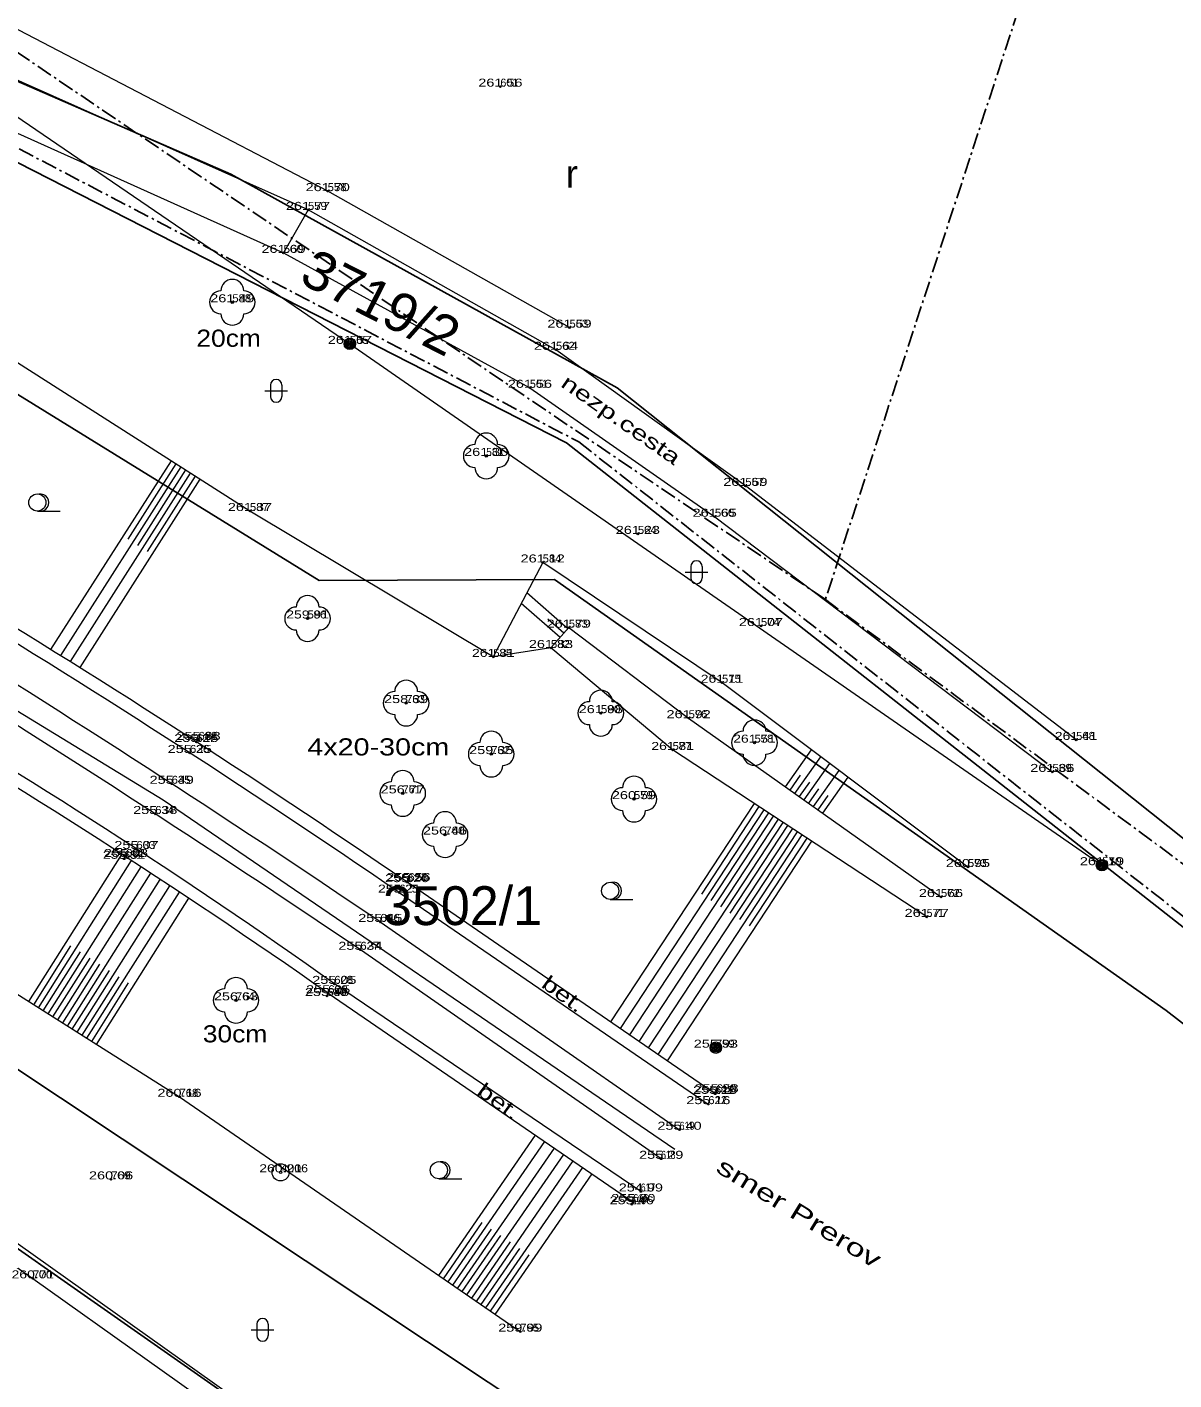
# Model space of a CAD drawing. Extents: x -568530 to -568223, y -1154101 to -1153740.
# Drawn here: x -568377.8 to -568327.6, y -1153975.4 to -1153916.3 of the extents above; entities that cross this region are included whole.
import ezdxf
from ezdxf.enums import TextEntityAlignment as Align

# ---------------------------------------------------------------- set-up
doc = ezdxf.new("R2010")
doc.units = 0
doc.header["$LTSCALE"] = 0.14
doc.header["$PDMODE"] = 32
doc.header["$PDSIZE"] = 0.07
doc.linetypes.add('DOT_DASHED', pattern=[7.7, 5, -1.2, 0.3, -1.2])
for name, color, linetype, lineweight in [('1', 7, 'Continuous', 25), ('11', 7, 'Continuous', 13), ('12', 7, 'Continuous', 13), ('14', 7, 'Continuous', 13), ('15', 7, 'Continuous', 13), ('21', 7, 'Continuous', 13), ('22', 7, 'Continuous', 13), ('23', 7, 'Continuous', 13), ('25', 7, 'Continuous', 13), ('36', 7, 'Continuous', 13), ('4', 7, 'Continuous', 25), ('42', 7, 'Continuous', 13), ('51', 7, 'Continuous', 13), ('52', 7, 'Continuous', 13), ('53', 7, 'Continuous', 13), ('6', 7, 'DOT_DASHED', 25), ('7', 7, 'Continuous', 13)]:
    doc.layers.add(name, color=color, linetype=linetype, lineweight=lineweight)
for name, color, linetype in [('13', 7, 'Continuous'), ('18', 7, 'Continuous'), ('40', 7, 'Continuous')]:
    doc.layers.add(name, color=color, linetype=linetype)

msp = doc.modelspace()

# ---------------------------------------------------------------- linework, layer by layer
at = {"layer": '1'}
for points in [[(-568393.92, -1153911.77), (-568368.85, -1153922.7), (-568351.96, -1153932.04), (-568287.81, -1153983.13)], [(-568397.85, -1153916.62), (-568382.3, -1153920.09), (-568354.17, -1153934.45), (-568269.88, -1154000.68)], [(-568381.21, -1153967.57), (-568365.54, -1153978.53), (-568303.79, -1154025.76)]]:
    msp.add_lwpolyline(points, dxfattribs=at)
at = {"layer": '11'}
for p, q in [((-568381.39, -1153919.46), (-568366.54, -1153926.14)), ((-568331.89, -1153947.44), (-568346.35, -1153936.33)), ((-568347.69, -1153937.68), (-568332.93, -1153948.84)), ((-568361.48, -1153954.12), (-568347.97, -1153963.37)), ((-568347.67, -1153962.92), (-568361.14, -1153953.66)), ((-568350.92, -1153967.19), (-568364.32, -1153958.11)), ((-568364.59, -1153958.52), (-568351.25, -1153967.65))]:
    msp.add_line(p, q, dxfattribs=at)
for points in [[(-568346.35, -1153936.33), (-568354.63, -1153930.38), (-568365.47, -1153924.26), (-568380.39, -1153917.61)], [(-568365.47, -1153924.26), (-568366.54, -1153926.14), (-568355.77, -1153932.04), (-568347.69, -1153937.68)]]:
    msp.add_lwpolyline(points, dxfattribs=at)
for centre, radius, start, end in [((-568603.2448, -1154307.4258), 428.6782, 55.61365, 58.88779), ((-568594.3404, -1154293.2988), 411.4198, 55.52877, 58.93604), ((-568515.3815, -1154170.2907), 260.4616, 54.55112, 59.87018), ((-568546.6395, -1154219.0038), 317.7953, 55.0507, 59.41916)]:
    msp.add_arc(centre, radius, start, end, dxfattribs=at)
for p in [(-568357.06, -1153918.87), (-568364.61, -1153923.44), (-568365.47, -1153924.26), (-568366.54, -1153926.14), (-568368.78, -1153928.3), (-568354.04, -1153929.41), (-568363.64, -1153930.12), (-568354.63, -1153930.38), (-568355.77, -1153932.04), (-568357.68, -1153935.02), (-568346.35, -1153936.33), (-568368.01, -1153937.43), (-568347.69, -1153937.68), (-568351.05, -1153938.43), (-568355.21, -1153939.68), (-568365.49, -1153942.13), (-568354.07, -1153942.53), (-568345.67, -1153942.46), (-568354.85, -1153943.42), (-568357.37, -1153943.81), (-568347.37, -1153944.94), (-568361.18, -1153945.83), (-568352.67, -1153946.27), (-568348.83, -1153946.49), (-568370.35, -1153947.53), (-568370.26, -1153947.44), (-568345.95, -1153947.56), (-568331.89, -1153947.44), (-568370.64, -1153948.01), (-568357.46, -1153948.06), (-568349.53, -1153947.88), (-568332.93, -1153948.84), (-568371.43, -1153949.36), (-568361.33, -1153949.78), (-568351.22, -1153950.03), (-568372.15, -1153950.68), (-568359.48, -1153951.58), (-568372.97, -1153952.21), (-568373.51, -1153952.64), (-568373.43, -1153952.56), (-568336.62, -1153953), (-568330.76, -1153952.92), (-568361.08, -1153953.61), (-568361.48, -1153954.12), (-568361.14, -1153953.66), (-568337.8, -1153954.31), (-568362.31, -1153955.4), (-568338.42, -1153955.18), (-568363.18, -1153956.62), (-568364.32, -1153958.11), (-568368.62, -1153958.83), (-568364.64, -1153958.64), (-568364.59, -1153958.52), (-568347.64, -1153960.9), (-568371.09, -1153963.05), (-568347.67, -1153962.92), (-568347.61, -1153962.85), (-568347.97, -1153963.37), (-568349.23, -1153964.49), (-568350.03, -1153965.76), (-568374.08, -1153966.66), (-568350.92, -1153967.19), (-568351.32, -1153967.75), (-568351.25, -1153967.65), (-568377.5, -1153970.99), (-568356.19, -1153973.32)]:
    msp.add_point(p, dxfattribs=at)
at = {"layer": '12'}
for p, q in [((-568362.31, -1153955.4), (-568349.23, -1153964.49)), ((-568350.03, -1153965.76), (-568363.18, -1153956.62))]:
    msp.add_line(p, q, dxfattribs=at)
for centre, radius, start, end in [((-568708.2241, -1154467.802), 618.2333, 55.97737, 58.24225), ((-568727.54, -1154497.0975), 651.8237, 56.01434, 58.14955)]:
    msp.add_arc(centre, radius, start, end, dxfattribs=at)
at = {"layer": '14'}
for points in [[(-568354.85, -1153943.42), (-568357.37, -1153943.81), (-568368.01, -1153937.43), (-568378.86, -1153930.51), (-568388.51, -1153923.88), (-568398.65, -1153916.93)], [(-568415.48, -1153937.58), (-568406.64, -1153941.73), (-568392.63, -1153949.25), (-568382.59, -1153955.78), (-568371.09, -1153963.05), (-568356.19, -1153973.32)], [(-568336.62, -1153953), (-568347.37, -1153944.94), (-568355.21, -1153939.68), (-568357.37, -1153943.81)], [(-568338.42, -1153955.18), (-568349.53, -1153947.88), (-568354.85, -1153943.42), (-568354.07, -1153942.53), (-568348.83, -1153946.49), (-568337.8, -1153954.31)]]:
    msp.add_lwpolyline(points, dxfattribs=at)
at = {"layer": '15'}
for p, q in [((-568371.459, -1153935.23), (-568376.724, -1153943.485)), ((-568371.038, -1153935.499), (-568376.299, -1153943.749)), ((-568370.616, -1153935.768), (-568375.875, -1153944.014)), ((-568371.248, -1153935.365), (-568373.354, -1153938.665)), ((-568370.827, -1153935.633), (-568372.931, -1153938.933)), ((-568370.195, -1153936.037), (-568375.452, -1153944.279)), ((-568370.405, -1153935.902), (-568372.509, -1153939.2)), ((-568354.116, -1153942.582), (-568355.907, -1153941.012)), ((-568354.445, -1153942.958), (-568356.145, -1153941.468)), ((-568354.281, -1153942.77), (-568354.979, -1153942.158)), ((-568344.601, -1153949.488), (-568343.457, -1153947.874)), ((-568344.193, -1153949.777), (-568343.056, -1153948.174)), ((-568343.785, -1153950.067), (-568342.656, -1153948.474)), ((-568343.377, -1153950.356), (-568342.256, -1153948.774)), ((-568344.397, -1153949.633), (-568343.941, -1153948.989)), ((-568343.989, -1153949.922), (-568343.536, -1153949.283)), ((-568342.969, -1153950.645), (-568341.856, -1153949.074)), ((-568343.581, -1153950.211), (-568343.131, -1153949.576)), ((-568343.173, -1153950.5), (-568342.726, -1153949.87)), ((-568345.966, -1153950.222), (-568352.243, -1153959.776)), ((-568345.548, -1153950.496), (-568351.831, -1153960.059)), ((-568345.757, -1153950.359), (-568348.269, -1153954.183)), ((-568345.339, -1153950.634), (-568347.854, -1153954.461)), ((-568345.13, -1153950.771), (-568351.419, -1153960.343)), ((-568344.712, -1153951.046), (-568351.007, -1153960.626)), ((-568344.921, -1153950.908), (-568347.438, -1153954.739)), ((-568344.503, -1153951.183), (-568347.022, -1153955.017)), ((-568344.294, -1153951.32), (-568350.595, -1153960.909)), ((-568343.877, -1153951.595), (-568350.183, -1153961.193)), ((-568344.085, -1153951.457), (-568346.607, -1153955.295)), ((-568343.668, -1153951.732), (-568346.191, -1153955.573)), ((-568343.459, -1153951.869), (-568349.771, -1153961.476)), ((-568377.676, -1153958.886), (-568373.605, -1153952.446)), ((-568377.254, -1153959.153), (-568373.186, -1153952.719)), ((-568376.831, -1153959.421), (-568372.767, -1153952.992)), ((-568376.409, -1153959.688), (-568372.349, -1153953.266)), ((-568375.986, -1153959.955), (-568371.931, -1153953.541)), ((-568375.563, -1153960.222), (-568371.513, -1153953.816)), ((-568375.141, -1153960.489), (-568371.096, -1153954.092)), ((-568374.718, -1153960.756), (-568370.68, -1153954.368)), ((-568377.465, -1153959.02), (-568375.837, -1153956.445)), ((-568377.043, -1153959.287), (-568375.416, -1153956.714)), ((-568376.62, -1153959.554), (-568374.995, -1153956.984)), ((-568376.197, -1153959.821), (-568374.574, -1153957.254)), ((-568375.775, -1153960.088), (-568374.154, -1153957.524)), ((-568375.352, -1153960.356), (-568373.733, -1153957.795)), ((-568374.929, -1153960.623), (-568373.313, -1153958.066)), ((-568359.757, -1153970.861), (-568355.526, -1153964.723)), ((-568359.346, -1153971.145), (-568355.114, -1153965.006)), ((-568358.934, -1153971.429), (-568354.701, -1153965.288)), ((-568358.522, -1153971.713), (-568354.289, -1153965.57)), ((-568358.11, -1153971.996), (-568353.876, -1153965.853)), ((-568357.699, -1153972.28), (-568353.463, -1153966.135)), ((-568357.287, -1153972.564), (-568353.051, -1153966.418)), ((-568359.551, -1153971.003), (-568357.859, -1153968.548)), ((-568359.14, -1153971.287), (-568357.447, -1153968.831)), ((-568358.728, -1153971.571), (-568357.035, -1153969.114)), ((-568358.316, -1153971.854), (-568356.623, -1153969.397)), ((-568357.905, -1153972.138), (-568356.211, -1153969.68)), ((-568357.493, -1153972.422), (-568355.799, -1153969.964))]:
    msp.add_line(p, q, dxfattribs=at)
at = {"layer": '21'}
for radius in [0.375, 0.05]:
    msp.add_circle((-568366.67, -1153966.35), radius, dxfattribs=at)
at = {"layer": '22'}
for centre in [(-568368.78, -1153928.3), (-568357.68, -1153935.02), (-568365.49, -1153942.13), (-568361.18, -1153945.83), (-568352.67, -1153946.27), (-568345.95, -1153947.56), (-568357.46, -1153948.06), (-568361.33, -1153949.78), (-568351.22, -1153950.03), (-568359.48, -1153951.58), (-568368.62, -1153958.83)]:
    msp.add_circle(centre, 0.05, dxfattribs=at)
for centre, start, end in [((-568368.78, -1153927.8), 0, 180), ((-568369.28, -1153928.3), 90, 270), ((-568368.28, -1153928.3), 270, 90), ((-568368.78, -1153928.8), 180, 0), ((-568357.68, -1153934.52), 0, 180), ((-568358.18, -1153935.02), 90, 270), ((-568357.18, -1153935.02), 270, 90), ((-568357.68, -1153935.52), 180, 0), ((-568365.49, -1153941.63), 0, 180), ((-568365.99, -1153942.13), 90, 270), ((-568364.99, -1153942.13), 270, 90), ((-568365.49, -1153942.63), 180, 0), ((-568361.68, -1153945.83), 90, 270), ((-568361.18, -1153945.33), 0, 180), ((-568360.68, -1153945.83), 270, 90), ((-568352.67, -1153945.77), 0, 180), ((-568353.17, -1153946.27), 90, 270), ((-568352.17, -1153946.27), 270, 90), ((-568361.18, -1153946.33), 180, 0), ((-568357.46, -1153947.56), 0, 180), ((-568352.67, -1153946.77), 180, 0), ((-568346.45, -1153947.56), 90, 270), ((-568345.95, -1153947.06), 0, 180), ((-568345.45, -1153947.56), 270, 90), ((-568357.96, -1153948.06), 90, 270), ((-568356.96, -1153948.06), 270, 90), ((-568345.95, -1153948.06), 180, 0), ((-568361.33, -1153949.28), 0, 180), ((-568357.46, -1153948.56), 180, 0), ((-568361.83, -1153949.78), 90, 270), ((-568360.83, -1153949.78), 270, 90), ((-568351.22, -1153949.53), 0, 180), ((-568351.72, -1153950.03), 90, 270), ((-568350.72, -1153950.03), 270, 90), ((-568361.33, -1153950.28), 180, 0), ((-568359.48, -1153951.08), 0, 180), ((-568351.22, -1153950.53), 180, 0), ((-568359.98, -1153951.58), 90, 270), ((-568358.98, -1153951.58), 270, 90), ((-568359.48, -1153952.08), 180, 0), ((-568369.12, -1153958.83), 90, 270), ((-568368.62, -1153958.33), 0, 180), ((-568368.12, -1153958.83), 270, 90), ((-568368.62, -1153959.33), 180, 0)]:
    msp.add_arc(centre, 0.5, start, end, dxfattribs=at)
at = {"layer": '23'}
msp.add_lwpolyline([(-568354.04, -1153929.41), (-568364.61, -1153923.44), (-568379.16, -1153915.86), (-568390.37, -1153909.46), (-568387.81, -1153906.15), (-568381.36, -1153897.16), (-568374.28, -1153888.42), (-568365.82, -1153877.84), (-568356.68, -1153865.62), (-568346.38, -1153852.31), (-568338.19, -1153841.21)], dxfattribs=at)
at = {"layer": '25'}
for centre, radius in [((-568363.64, -1153930.12), 0.25), ((-568363.64, -1153930.12), 0.2), ((-568363.64, -1153930.12), 0.15), ((-568363.64, -1153930.12), 0.1), ((-568363.64, -1153930.12), 0.05), ((-568330.76, -1153952.92), 0.25), ((-568330.76, -1153952.92), 0.2), ((-568330.76, -1153952.92), 0.15), ((-568330.76, -1153952.92), 0.1), ((-568330.76, -1153952.92), 0.05), ((-568347.64, -1153960.9), 0.25), ((-568347.64, -1153960.9), 0.2), ((-568347.64, -1153960.9), 0.15), ((-568347.64, -1153960.9), 0.1), ((-568347.64, -1153960.9), 0.05)]:
    msp.add_circle(centre, radius, dxfattribs=at)
at = {"layer": '36'}
for p, q in [((-568367.362, -1153932.17), (-568366.362, -1153932.17)), ((-568367.112, -1153931.92), (-568367.112, -1153932.42)), ((-568366.612, -1153931.92), (-568366.612, -1153932.42)), ((-568377.303, -1153937.435), (-568376.303, -1153937.435)), ((-568348.735, -1153939.858), (-568348.735, -1153940.358)), ((-568348.235, -1153939.858), (-568348.235, -1153940.358)), ((-568348.985, -1153940.108), (-568347.985, -1153940.108)), ((-568352.263, -1153954.415), (-568351.263, -1153954.415)), ((-568359.75, -1153966.636), (-568358.75, -1153966.636)), ((-568367.708, -1153972.99), (-568367.708, -1153973.49)), ((-568367.208, -1153972.99), (-568367.208, -1153973.49)), ((-568367.958, -1153973.24), (-568366.958, -1153973.24))]:
    msp.add_line(p, q, dxfattribs=at)
for centre in [(-568377.3024, -1153937.0594), (-568352.2624, -1153954.039), (-568359.7499, -1153966.2605)]:
    msp.add_circle(centre, 0.375, dxfattribs=at)
for centre, radius, start, end in [((-568366.8622, -1153931.921), 0.25, 0, 180), ((-568366.8622, -1153932.421), 0.25, 180, 0), ((-568377.1774, -1153937.0594), 0.375, 260.40593, 99.59407), ((-568348.4848, -1153939.8588), 0.25, 0, 180), ((-568348.4848, -1153940.3588), 0.25, 180, 0), ((-568352.1374, -1153954.039), 0.375, 260.40593, 99.59407), ((-568359.6249, -1153966.2605), 0.375, 260.40593, 99.59407), ((-568367.4571, -1153972.991), 0.25, 0, 180), ((-568367.4571, -1153973.491), 0.25, 180, 0)]:
    msp.add_arc(centre, radius, start, end, dxfattribs=at)
at = {"layer": '4'}
for points in [[(-568416.66, -1153938.36), (-568411.09, -1153926.18), (-568408.89, -1153922.6), (-568403.83, -1153916.49), (-568364.99, -1153940.47), (-568354.7, -1153940.43), (-568327.96, -1153959.28), (-568308.58, -1153974.27), (-568269.22, -1154006.01)], [(-568416.35, -1153942.92), (-568411.96, -1153940.51), (-568386.96, -1153956.01), (-568354.94, -1153977.29), (-568293.66, -1154026.45)]]:
    msp.add_lwpolyline(points, dxfattribs=at)
at = {"layer": '51'}
msp.add_lwpolyline([(-568419.22, -1153887.66), (-568408.38, -1153895.39), (-568389.55, -1153912.42), (-568363.64, -1153930.12), (-568330.76, -1153952.92)], dxfattribs=at)
at = {"layer": '52'}
msp.add_lwpolyline([(-568440.61, -1153926.76), (-568414.88, -1153944.05), (-568397.12, -1153956.51), (-568380.33, -1153967.93), (-568365.972, -1153978.132)], dxfattribs=at)
at = {"layer": '53'}
msp.add_lwpolyline([(-568433.578, -1153915.068), (-568419.78, -1153922.17), (-568410.54, -1153927.14), (-568389.55, -1153939.23), (-568371.805, -1153950.061), (-568349.435, -1153965.343)], dxfattribs=at)
at = {"layer": '6'}
for p, q in [((-568382.13, -1153919.48), (-568353.63, -1153934.41)), ((-568353.63, -1153934.41), (-568280.65, -1153991.71)), ((-568342.85, -1153941.3), (-568294.79, -1153976.84))]:
    msp.add_line(p, q, dxfattribs=at)
msp.add_lwpolyline([(-568292.75, -1153788.12), (-568342.85, -1153941.3), (-568385.34, -1153912.52), (-568390.25, -1153908.12)], dxfattribs=at)
at = {"layer": '7'}
msp.add_lwpolyline([(-568397.3, -1153957.22), (-568391.53, -1153961.19), (-568377.5, -1153970.99), (-568362.5, -1153981.67)], dxfattribs=at)

# ---------------------------------------------------------------- texts
at = {"layer": '12'}
for s, width, p in [('261.56', 1.35, (-568357.06, -1153918.87)), ('261.70', 1.35, (-568364.6095, -1153923.44)), ('261.77', 1.35, (-568365.47, -1153924.26)), ('261.69', 1.35, (-568366.54, -1153926.14)), ('261.49', 1.35, (-568368.78, -1153928.3)), ('261.59', 1.35, (-568354.04, -1153929.41)), ('261.57', 1.35, (-568363.64, -1153930.12)), ('261.64', 1.35, (-568354.63, -1153930.38)), ('261.56', 1.35, (-568355.77, -1153932.04)), ('261.30', 1.35, (-568357.6795, -1153935.02)), ('261.59', 1.35, (-568346.35, -1153936.33)), ('261.37', 1.35, (-568368.01, -1153937.43)), ('261.65', 1.35, (-568347.6905, -1153937.68)), ('261.23', 1.35, (-568351.05, -1153938.43)), ('261.12', 1.35, (-568355.21, -1153939.68)), ('259.91', 1.3, (-568365.49, -1153942.13)), ('261.79', 1.35, (-568354.07, -1153942.53)), ('261.07', 1.35, (-568345.67, -1153942.46)), ('261.31', 1.3, (-568357.37, -1153943.81)), ('261.83', 1.35, (-568354.85, -1153943.42)), ('261.11', 1.3, (-568347.37, -1153944.94)), ('258.39', 1.35, (-568361.18, -1153945.83)), ('261.98', 1.35, (-568352.67, -1153946.27)), ('261.92', 1.35, (-568348.83, -1153946.49)), ('255.68', 1.35, (-568370.26, -1153947.44)), ('261.41', 1.3, (-568331.89, -1153947.44)), ('255.25', 1.35, (-568370.6405, -1153948.01)), ('255.25', 1.35, (-568370.3505, -1153947.53)), ('259.35', 1.35, (-568357.4605, -1153948.06)), ('261.81', 1.3, (-568349.53, -1153947.88)), ('261.51', 1.3, (-568345.95, -1153947.56)), ('261.36', 1.35, (-568332.93, -1153948.84)), ('255.49', 1.35, (-568371.43, -1153949.36)), ('256.77', 1.35, (-568361.33, -1153949.78)), ('260.59', 1.35, (-568351.22, -1153950.03)), ('255.38', 1.35, (-568372.15, -1153950.68)), ('256.46', 1.35, (-568359.48, -1153951.58)), ('255.51', 1.3, (-568373.51, -1153952.64)), ('255.08', 1.35, (-568373.43, -1153952.56)), ('255.07', 1.35, (-568372.97, -1153952.21)), ('260.95', 1.35, (-568336.6205, -1153953)), ('261.19', 1.35, (-568330.76, -1153952.92)), ('255.20', 1.35, (-568361.1395, -1153953.66)), ('255.56', 1.35, (-568361.08, -1153953.61)), ('255.21', 1.3, (-568361.48, -1153954.12)), ('261.66', 1.35, (-568337.8, -1153954.31)), ('255.45', 1.35, (-568362.3105, -1153955.4)), ('261.77', 1.35, (-568338.42, -1153955.18)), ('255.34', 1.35, (-568363.18, -1153956.62)), ('255.05', 1.35, (-568364.3205, -1153958.11)), ('255.46', 1.35, (-568364.64, -1153958.64)), ('255.05', 1.35, (-568364.5905, -1153958.52)), ('256.63', 1.35, (-568368.62, -1153958.83)), ('255.93', 1.35, (-568347.64, -1153960.9)), ('255.58', 1.35, (-568347.61, -1153962.85)), ('260.16', 1.35, (-568371.09, -1153963.05)), ('255.16', 1.35, (-568347.97, -1153963.37)), ('255.15', 1.35, (-568347.6705, -1153962.92)), ('255.40', 1.35, (-568349.2295, -1153964.49)), ('255.29', 1.35, (-568350.03, -1153965.76)), ('260.06', 1.35, (-568374.08, -1153966.66)), ('254.99', 1.35, (-568350.92, -1153967.19)), ('255.46', 1.35, (-568351.32, -1153967.75)), ('255.00', 1.35, (-568351.2495, -1153967.65)), ('260.01', 1.3, (-568377.5, -1153970.99)), ('259.99', 1.35, (-568356.19, -1153973.32))]:
    msp.add_text(s, height=0.35, dxfattribs=dict(at, width=width)).set_placement(p, align=Align.CENTER)
at = {"layer": '13'}
for s, p in [('601', (-568357.06, -1153918.87)), ('561', (-568355.77, -1153932.04)), ('761', (-568361.33, -1153949.78)), ('631', (-568373.51, -1153952.64)), ('621', (-568347.67, -1153962.92))]:
    msp.add_text(s, height=0.35, dxfattribs=at).set_placement(p)
for s, width, p in [('558', 1.05, (-568364.61, -1153923.44)), ('559', 1.05, (-568365.47, -1153924.26)), ('560', 1.1, (-568366.54, -1153926.14)), ('588', 1.05, (-568368.78, -1153928.3)), ('563', 1.05, (-568354.04, -1153929.41)), ('565', 1.05, (-568363.64, -1153930.12)), ('562', 1.05, (-568354.63, -1153930.38)), ('581', 0.95, (-568357.68, -1153935.02)), ('567', 1.05, (-568346.35, -1153936.33)), ('587', 1.05, (-568368.01, -1153937.43)), ('566', 1.1, (-568347.69, -1153937.68)), ('564', 1.05, (-568351.05, -1153938.43)), ('584', 1.05, (-568355.21, -1153939.68)), ('586', 1.05, (-568365.49, -1153942.13)), ('583', 1.05, (-568354.07, -1153942.53)), ('574', 1.05, (-568345.67, -1153942.46)), ('585', 1.05, (-568357.37, -1153943.81)), ('582', 1.05, (-568354.85, -1153943.42)), ('575', 1.05, (-568347.37, -1153944.94)), ('763', 1.05, (-568361.18, -1153945.83)), ('580', 1.1, (-568352.67, -1153946.27)), ('576', 1.05, (-568348.83, -1153946.49)), ('638', 1.05, (-568370.26, -1153947.44)), ('568', 1.05, (-568331.89, -1153947.44)), ('636', 1.1, (-568370.64, -1153948.01)), ('637', 1.05, (-568370.35, -1153947.53)), ('762', 1.05, (-568357.46, -1153948.06)), ('577', 1.05, (-568349.53, -1153947.88)), ('578', 1.05, (-568345.95, -1153947.56)), ('569', 1.1, (-568332.93, -1153948.84)), ('635', 1.05, (-568371.43, -1153949.36)), ('579', 1.05, (-568351.22, -1153950.03)), ('634', 1.05, (-568372.15, -1153950.68)), ('760', 1.1, (-568359.48, -1153951.58)), ('632', 1.05, (-568373.43, -1153952.56)), ('633', 1.05, (-568372.97, -1153952.21)), ('573', 1.05, (-568336.62, -1153953)), ('570', 1.1, (-568330.76, -1153952.92)), ('624', 1.05, (-568361.14, -1153953.66)), ('623', 1.05, (-568361.08, -1153953.61)), ('625', 1.05, (-568361.48, -1153954.12)), ('572', 1.05, (-568337.8, -1153954.31)), ('626', 1.1, (-568362.31, -1153955.4)), ('571', 0.95, (-568338.42, -1153955.18)), ('627', 1.05, (-568363.18, -1153956.62)), ('628', 1.05, (-568364.32, -1153958.11)), ('630', 1.1, (-568364.64, -1153958.64)), ('629', 1.1, (-568364.59, -1153958.52)), ('764', 1.05, (-568368.62, -1153958.83)), ('759', 1.05, (-568347.64, -1153960.9)), ('620', 1.1, (-568347.61, -1153962.85)), ('768', 1.05, (-568371.09, -1153963.05)), ('622', 1.05, (-568347.97, -1153963.37)), ('619', 0.85, (-568349.23, -1153964.49)), ('618', 0.8, (-568350.03, -1153965.76)), ('769', 1.1, (-568374.08, -1153966.66)), ('617', 0.8, (-568350.92, -1153967.19)), ('615', 0.8, (-568351.32, -1153967.75)), ('616', 0.85, (-568351.25, -1153967.65)), ('770', 1.1, (-568377.5, -1153970.99)), ('765', 1.05, (-568356.19, -1153973.32))]:
    msp.add_text(s, height=0.35, dxfattribs=dict(at, width=width)).set_placement(p)
at = {"layer": '18', "width": 1.05}
msp.add_text('3719/2', height=1.7, rotation=333.103, dxfattribs=at).set_placement((-568365.922, -1153927.413))
at = {"layer": '18'}
msp.add_text('3502/1', height=1.7, dxfattribs=at).set_placement((-568362.19, -1153955.54))
at = {"layer": '22', "width": 1.3}
msp.add_text('260.21', height=0.35, dxfattribs=at).set_placement((-568366.67, -1153966.35), align=Align.CENTER)
at = {"layer": '23', "width": 1.15}
msp.add_text('4006', height=0.35, dxfattribs=at).set_placement((-568366.67, -1153966.35))
at = {"layer": '36'}
msp.add_text('r', height=1.2, dxfattribs=at).set_placement((-568353.9335, -1153923.281), align=Align.CENTER)
at = {"layer": '40'}
for s, rotation, width, p in [('nezp.cesta', 325.064, 1.45, (-568354.467, -1153931.957)), ('bet.', 323.922, 1.4, (-568355.318, -1153958.219)), ('bet.', 323.922, 1.4, (-568358.138, -1153962.914))]:
    msp.add_text(s, height=0.65, rotation=rotation, dxfattribs=dict(at, width=width)).set_placement(p)
at = {"layer": '42'}
for s, width, p in [('20cm', 1.15, (-568368.942, -1153930.247)), ('4x20-30cm', 1.25, (-568362.3975, -1153948.12)), ('30cm', 1.15, (-568368.661, -1153960.669))]:
    msp.add_text(s, height=0.75, dxfattribs=dict(at, width=width)).set_placement(p, align=Align.CENTER)
at = {"layer": '42', "width": 1.5}
msp.add_text('smer Prerov', height=0.75, rotation=328.512, dxfattribs=at).set_placement((-568344.1979, -1153968.4377), align=Align.CENTER)

doc.saveas('drawing.dxf')
